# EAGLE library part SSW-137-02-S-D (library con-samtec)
THROUGH-HOLE .025" SQ POST SOCKET Source: Samtec SSW.pdf
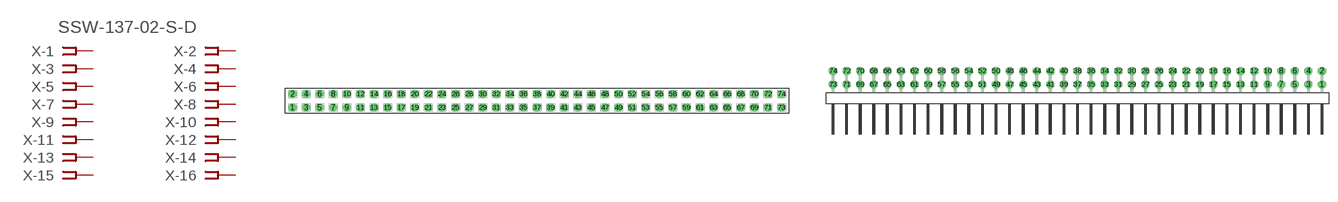
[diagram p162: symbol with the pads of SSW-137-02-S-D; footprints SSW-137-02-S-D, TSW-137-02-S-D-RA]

Designator prefix X; gates -1=FPINV -2=FPIN -3=FPIN -4=FPIN -5=FPIN -6=FPIN -7=FPIN -8=FPIN -9=FPIN -10=FPIN -11=FPIN -12=FPIN -13=FPIN -14=FPIN -15=FPIN -16=FPIN -17=FPIN -18=FPIN -19=FPIN -20=FPIN -21=FPIN -22=FPIN -23=FPIN -24=FPIN -25=FPIN -26=FPIN -27=FPIN -28=FPIN -29=FPIN -30=FPIN -31=FPIN -32=FPIN -33=FPIN -34=FPIN -35=FPIN -36=FPIN -37=FPIN -38=FPIN -39=FPIN -40=FPIN -41=FPIN -42=FPIN -43=FPIN -44=FPIN -45=FPIN -46=FPIN -47=FPIN -48=FPIN -49=FPIN -50=FPIN -51=FPIN -52=FPIN -53=FPIN -54=FPIN -55=FPIN -56=FPIN -57=FPIN -58=FPIN -59=FPIN -60=FPIN -61=FPIN -62=FPIN -63=FPIN -64=FPIN -65=FPIN -66=FPIN -67=FPIN -68=FPIN -69=FPIN -70=FPIN -71=FPIN -72=FPIN -73=FPIN -74=FPIN

## SSW-137-02-S-D (OC_FARNELL: unknown; OC_NEWARK: unknown)  [SSW-137-02-S-D]
1  -1:1  pas
2  -2:1  pas
3  -3:1  pas
4  -4:1  pas
5  -5:1  pas
6  -6:1  pas
7  -7:1  pas
8  -8:1  pas
9  -9:1  pas
10  -10:1  pas
11  -11:1  pas
12  -12:1  pas
13  -13:1  pas
14  -14:1  pas
15  -15:1  pas
16  -16:1  pas
17  -17:1  pas
18  -18:1  pas
19  -19:1  pas
20  -20:1  pas
21  -21:1  pas
22  -22:1  pas
23  -23:1  pas
24  -24:1  pas
25  -25:1  pas
26  -26:1  pas
27  -27:1  pas
28  -28:1  pas
29  -29:1  pas
30  -30:1  pas
31  -31:1  pas
32  -32:1  pas
33  -33:1  pas
34  -34:1  pas
35  -35:1  pas
36  -36:1  pas
37  -37:1  pas
38  -38:1  pas
39  -39:1  pas
40  -40:1  pas
41  -41:1  pas
42  -42:1  pas
43  -43:1  pas
44  -44:1  pas
45  -45:1  pas
46  -46:1  pas
47  -47:1  pas
48  -48:1  pas
49  -49:1  pas
50  -50:1  pas
51  -51:1  pas
52  -52:1  pas
53  -53:1  pas
54  -54:1  pas
55  -55:1  pas
56  -56:1  pas
57  -57:1  pas
58  -58:1  pas
59  -59:1  pas
60  -60:1  pas
61  -61:1  pas
62  -62:1  pas
63  -63:1  pas
64  -64:1  pas
65  -65:1  pas
66  -66:1  pas
67  -67:1  pas
68  -68:1  pas
69  -69:1  pas
70  -70:1  pas
71  -71:1  pas
72  -72:1  pas
73  -73:1  pas
74  -74:1  pas

## SSW-137-02-S-D-RA (OC_FARNELL: unknown; OC_NEWARK: unknown)  [TSW-137-02-S-D-RA]
Pads as for SSW-137-02-S-D

## Footprint SSW-137-02-S-D (pad centres in mm)
THROUGH-HOLE .025" SQ POST SOCKET Source: Samtec SSW.pdf
drill 1 pad 1.5 octagon: 1 -45.72,-1.27; 2 -45.72,1.27; 3 -43.18,-1.27; 4 -43.18,1.27; 5 -40.64,-1.27; 6 -40.64,1.27; 7 -38.1,-1.27; 8 -38.1,1.27; 9 -35.56,-1.27; 10 -35.56,1.27; 11 -33.02,-1.27; 12 -33.02,1.27; 13 -30.48,-1.27; 14 -30.48,1.27; 15 -27.94,-1.27; 16 -27.94,1.27; 17 -25.4,-1.27; 18 -25.4,1.27; 19 -22.86,-1.27; 20 -22.86,1.27; 21 -20.32,-1.27; 22 -20.32,1.27; 23 -17.78,-1.27; 24 -17.78,1.27; 25 -15.24,-1.27; 26 -15.24,1.27; 27 -12.7,-1.27; 28 -12.7,1.27; 29 -10.16,-1.27; 30 -10.16,1.27; 31 -7.62,-1.27; 32 -7.62,1.27; 33 -5.08,-1.27; 34 -5.08,1.27; 35 -2.54,-1.27; 36 -2.54,1.27; 37 0,-1.27; 38 0,1.27; 39 2.54,-1.27; 40 2.54,1.27; 41 5.08,-1.27; 42 5.08,1.27; 43 7.62,-1.27; 44 7.62,1.27; 45 10.16,-1.27; 46 10.16,1.27; 47 12.7,-1.27; 48 12.7,1.27; 49 15.24,-1.27; 50 15.24,1.27; 51 17.78,-1.27; 52 17.78,1.27; 53 20.32,-1.27; 54 20.32,1.27; 55 22.86,-1.27; 56 22.86,1.27; 57 25.4,-1.27; 58 25.4,1.27; 59 27.94,-1.27; 60 27.94,1.27; 61 30.48,-1.27; 62 30.48,1.27; 63 33.02,-1.27; 64 33.02,1.27; 65 35.56,-1.27; 66 35.56,1.27; 67 38.1,-1.27; 68 38.1,1.27; 69 40.64,-1.27; 70 40.64,1.27; 71 43.18,-1.27; 72 43.18,1.27; 73 45.72,-1.27; 74 45.72,1.27

## Footprint TSW-137-02-S-D-RA (pad centres in mm)
THROUGH-HOLE .025" SQ POST HEADER Source: Samtec TSW.pdf
drill 1 pad 1.5 octagon: 1 45.72,1.524; 2 45.72,4.064; 3 43.18,1.524; 4 43.18,4.064; 5 40.64,1.524; 6 40.64,4.064; 7 38.1,1.524; 8 38.1,4.064; 9 35.56,1.524; 10 35.56,4.064; 11 33.02,1.524; 12 33.02,4.064; 13 30.48,1.524; 14 30.48,4.064; 15 27.94,1.524; 16 27.94,4.064; 17 25.4,1.524; 18 25.4,4.064; 19 22.86,1.524; 20 22.86,4.064; 21 20.32,1.524; 22 20.32,4.064; 23 17.78,1.524; 24 17.78,4.064; 25 15.24,1.524; 26 15.24,4.064; 27 12.7,1.524; 28 12.7,4.064; 29 10.16,1.524; 30 10.16,4.064; 31 7.62,1.524; 32 7.62,4.064; 33 5.08,1.524; 34 5.08,4.064; 35 2.54,1.524; 36 2.54,4.064; 37 0,1.524; 38 0,4.064; 39 -2.54,1.524; 40 -2.54,4.064; 41 -5.08,1.524; 42 -5.08,4.064; 43 -7.62,1.524; 44 -7.62,4.064; 45 -10.16,1.524; 46 -10.16,4.064; 47 -12.7,1.524; 48 -12.7,4.064; 49 -15.24,1.524; 50 -15.24,4.064; 51 -17.78,1.524; 52 -17.78,4.064; 53 -20.32,1.524; 54 -20.32,4.064; 55 -22.86,1.524; 56 -22.86,4.064; 57 -25.4,1.524; 58 -25.4,4.064; 59 -27.94,1.524; 60 -27.94,4.064; 61 -30.48,1.524; 62 -30.48,4.064; 63 -33.02,1.524; 64 -33.02,4.064; 65 -35.56,1.524; 66 -35.56,4.064; 67 -38.1,1.524; 68 -38.1,4.064; 69 -40.64,1.524; 70 -40.64,4.064; 71 -43.18,1.524; 72 -43.18,4.064; 73 -45.72,1.524; 74 -45.72,4.064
